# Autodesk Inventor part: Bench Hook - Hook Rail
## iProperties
Created: 2010-02
Part Number: Bench Hook - Hook Rail
Document SubType Name: Modeling
Designer: Munford
Density: 1 g/cm^3
Length: 200.000 mm
Width: 44.000 mm
Thickness: 19.000 mm
Author: Munford
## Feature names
1. Extrusion1
